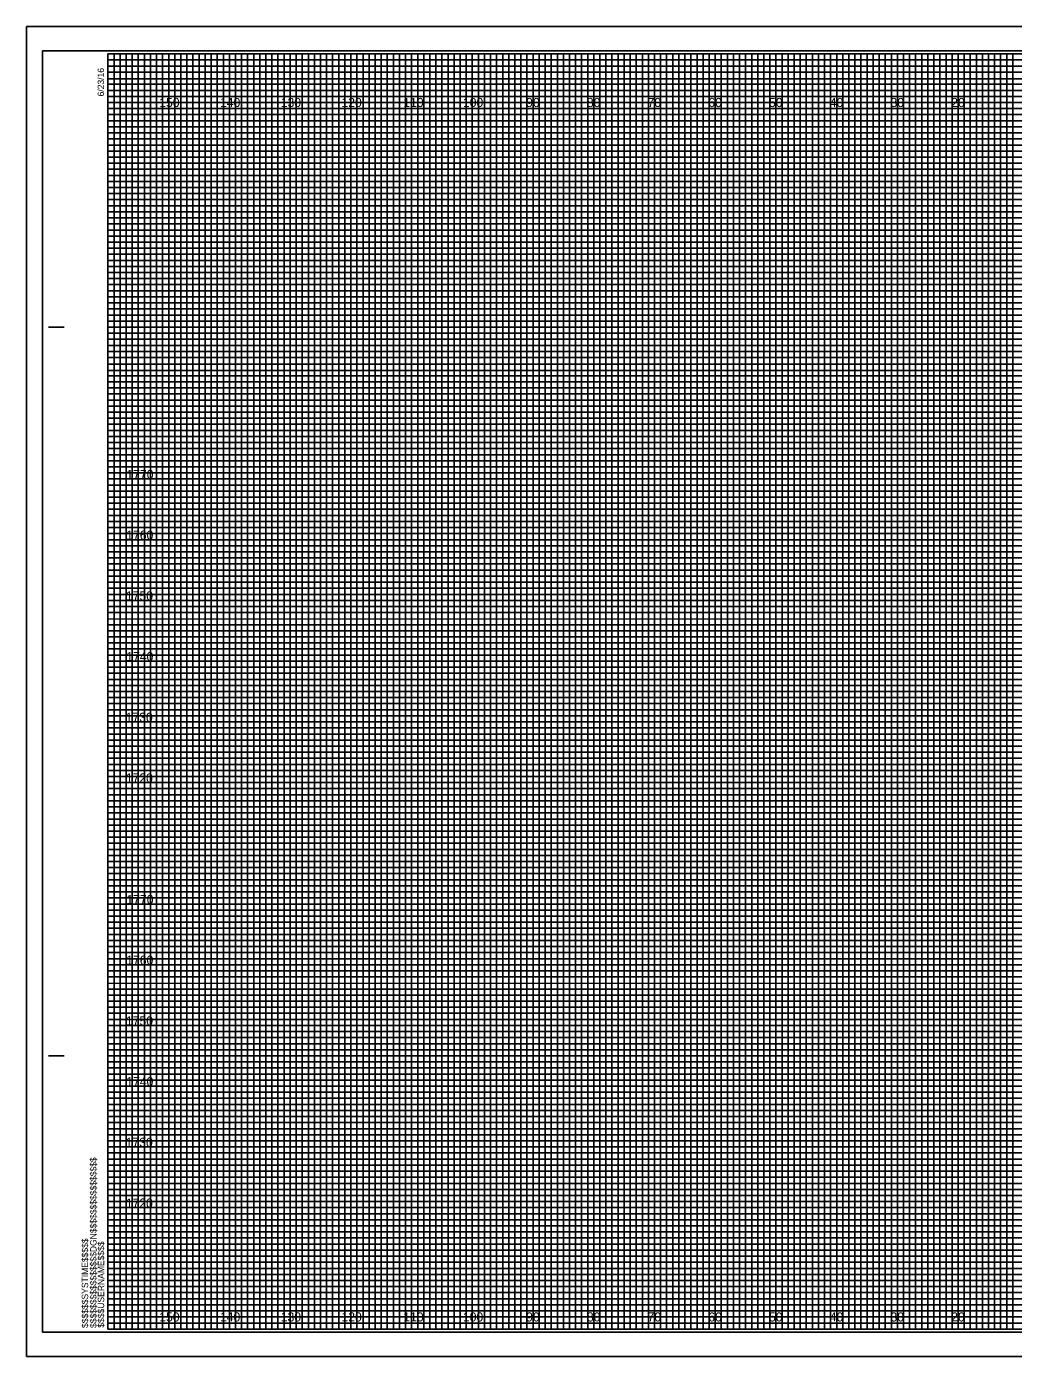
# Model space of a CAD drawing. Extents: x 570 to 907, y -9 to 870.
# Drawn here: x 570.4 to 732.9, y 210.6 to 429.6 of the extents above; entities that cross this region are included whole.
import ezdxf

# ---------------------------------------------------------------- set-up
doc = ezdxf.new("R2010")
doc.units = 0
for name, color, linetype in [('Prop XS Earthwork Shape', 7, 'Continuous'), ('Raster_Level_0', 7, 'Continuous'), ('Scratch_Level_3', 7, 'Continuous'), ('Sheet Cross Section CELL', 7, 'Continuous'), ('Sheet Cross Section Grid Middle CELL', 7, 'Continuous'), ('Sheet Cross Section Grid Minor 1 CELL', 7, 'Continuous'), ('Sheet Cross Section Grid Minor 2 CELL', 7, 'Continuous'), ('Sheet Cutting Line CELL', 7, 'Continuous'), ('Sheet DOT Grid CELL', 7, 'Continuous'), ('Sheet Plot Border Inside CELL', 7, 'Continuous'), ('Sheet Plot Border Outside CELL', 7, 'Continuous')]:
    doc.layers.add(name, color=color, linetype=linetype)

msp = doc.modelspace()

# ---------------------------------------------------------------- linework, layer by layer
at = {"layer": 'Prop XS Earthwork Shape'}
for p, q in [((593.77, 425.14), (583.77, 425.14)), ((593.77, 215.14), (593.77, 425.14)), ((613.77, 425.14), (603.77, 425.14)), ((603.77, 425.14), (603.77, 215.14)), ((613.77, 215.14), (613.77, 425.14)), ((633.77, 425.14), (623.77, 425.14)), ((623.77, 425.14), (623.77, 215.14)), ((633.77, 215.14), (633.77, 425.14)), ((653.77, 425.14), (643.77, 425.14)), ((643.77, 425.14), (643.77, 215.14)), ((653.77, 215.14), (653.77, 425.14)), ((673.77, 425.14), (663.77, 425.14)), ((663.77, 425.14), (663.77, 215.14)), ((673.77, 215.14), (673.77, 425.14)), ((693.77, 425.14), (683.77, 425.14)), ((683.77, 425.14), (683.77, 215.14)), ((693.77, 215.14), (693.77, 425.14)), ((713.77, 425.14), (703.77, 425.14)), ((703.77, 425.14), (703.77, 215.14)), ((713.77, 215.14), (713.77, 425.14)), ((733.77, 425.14), (723.77, 425.14)), ((723.77, 425.14), (723.77, 215.14)), ((603.77, 215.14), (593.77, 215.14)), ((623.77, 215.14), (613.77, 215.14)), ((643.77, 215.14), (633.77, 215.14)), ((663.77, 215.14), (653.77, 215.14)), ((683.77, 215.14), (673.77, 215.14)), ((703.77, 215.14), (693.77, 215.14)), ((723.77, 215.14), (713.77, 215.14))]:
    msp.add_line(p, q, dxfattribs=at)
for points in [[(583.77, 415.14), (903.77, 415.14), (903.77, 405.14), (583.77, 405.14)], [(583.77, 395.14), (903.77, 395.14), (903.77, 385.14), (583.77, 385.14)], [(583.77, 375.14), (903.77, 375.14), (903.77, 365.14), (583.77, 365.14)], [(583.77, 355.14), (903.77, 355.14), (903.77, 345.14), (583.77, 345.14)], [(583.77, 335.14), (903.77, 335.14), (903.77, 325.14), (583.77, 325.14)], [(583.77, 315.14), (903.77, 315.14), (903.77, 305.14), (583.77, 305.14)], [(583.77, 295.14), (903.77, 295.14), (903.77, 285.14), (583.77, 285.14)], [(583.77, 275.14), (903.77, 275.14), (903.77, 265.14), (583.77, 265.14)], [(583.77, 255.14), (903.77, 255.14), (903.77, 245.14), (583.77, 245.14)], [(583.77, 235.14), (903.77, 235.14), (903.77, 225.14), (583.77, 225.14)]]:
    msp.add_lwpolyline(points, dxfattribs=at)
at = {"layer": 'Sheet Cross Section CELL'}
for p, q in [((573.97, 380.14), (576.47, 380.14)), ((574.07, 380.14), (576.57, 380.14)), ((573.97, 260.14), (576.47, 260.14)), ((574.07, 260.14), (576.57, 260.14)), ((583.77, 215.14), (583.77, 215.14)), ((583.77, 215.14), (583.77, 215.14)), ((583.77, 215.14), (583.77, 215.14)), ((583.77, 215.14), (583.77, 215.14)), ((583.77, 215.14), (583.77, 215.14)), ((583.77, 215.14), (583.77, 215.14)), ((583.77, 215.14), (583.77, 215.14))]:
    msp.add_line(p, q, dxfattribs=at)
msp.add_lwpolyline([(903.77, 425.14), (583.77, 425.14), (583.77, 215.14), (903.77, 215.14)], close=True, dxfattribs=at)
at = {"layer": 'Sheet Cross Section Grid Middle CELL'}
for points in [[(583.77, 425.14), (588.77, 425.14), (588.77, 215.14), (598.77, 215.14), (598.77, 425.14), (608.77, 425.14), (608.77, 215.14), (618.77, 215.14), (618.77, 425.14), (628.77, 425.14), (628.77, 215.14), (638.77, 215.14), (638.77, 425.14), (648.77, 425.14), (648.77, 215.14), (658.77, 215.14), (658.77, 425.14), (668.77, 425.14), (668.77, 215.14), (678.77, 215.14), (678.77, 425.14), (688.77, 425.14), (688.77, 215.14), (698.77, 215.14), (698.77, 425.14), (708.77, 425.14), (708.77, 215.14), (718.77, 215.14), (718.77, 425.14), (728.77, 425.14), (728.77, 215.14), (738.77, 215.14)], [(583.77, 420.14), (858.77, 420.14)], [(583.77, 400.14), (903.77, 400.14), (903.77, 410.14), (583.77, 410.14)], [(583.77, 380.14), (903.77, 380.14), (903.77, 390.14), (583.77, 390.14)], [(583.77, 360.14), (903.77, 360.14), (903.77, 370.14), (583.77, 370.14)], [(583.77, 340.14), (903.77, 340.14), (903.77, 350.14), (583.77, 350.14)], [(583.77, 320.14), (903.77, 320.14), (903.77, 330.14), (583.77, 330.14)], [(583.77, 300.14), (903.77, 300.14), (903.77, 310.14), (583.77, 310.14)], [(583.77, 280.14), (903.77, 280.14), (903.77, 290.14), (583.77, 290.14)], [(583.77, 260.14), (903.77, 260.14), (903.77, 270.14), (583.77, 270.14)], [(583.77, 240.14), (903.77, 240.14), (903.77, 250.14), (583.77, 250.14)], [(583.77, 220.14), (903.77, 220.14), (903.77, 230.14), (583.77, 230.14)]]:
    msp.add_lwpolyline(points, dxfattribs=at)
at = {"layer": 'Sheet Cross Section Grid Minor 1 CELL'}
for p, q in [((583.77, 424.14), (843.77, 424.14)), ((843.77, 423.12), (583.77, 423.12)), ((583.77, 423.12), (583.77, 422.14)), ((583.77, 422.14), (843.77, 422.14)), ((843.77, 421.03), (583.77, 421.03)), ((583.77, 421.03), (583.77, 419.14)), ((583.77, 419.14), (903.77, 419.14))]:
    msp.add_line(p, q, dxfattribs=at)
for points in [[(583.77, 418.14), (853.77, 418.14), (903.77, 418.14), (903.77, 417.14), (583.77, 417.14)], [(583.77, 416.14), (903.77, 416.14), (903.77, 414.14), (583.77, 414.14)], [(583.77, 413.14), (903.77, 413.14), (903.77, 412.14), (583.77, 412.12)], [(583.77, 411.14), (903.77, 411.14), (903.77, 409.14), (583.77, 409.14)], [(583.77, 408.14), (903.77, 408.14), (903.77, 407.14), (583.77, 407.14)], [(583.77, 406.14), (903.77, 406.14), (903.77, 404.14), (583.77, 404.14)], [(583.77, 403.14), (903.77, 403.14), (903.77, 402.14), (583.77, 402.14)], [(583.77, 401.14), (903.77, 401.14), (903.77, 399.14), (583.77, 399.14)], [(583.77, 398.14), (903.77, 398.14), (903.77, 397.14), (583.77, 397.14)], [(583.77, 396.14), (903.77, 396.14), (903.77, 394.14), (583.77, 394.14)], [(583.77, 393.14), (903.77, 393.14), (903.77, 392.14), (583.77, 392.14)], [(583.77, 391.14), (903.77, 391.14), (903.77, 389.09), (903.77, 388.14), (903.77, 387.14), (583.77, 387.14)], [(583.77, 389.14), (903.77, 389.14), (903.77, 388.14), (583.77, 388.14)], [(583.77, 386.14), (903.77, 386.14), (903.77, 384.14), (583.77, 384.17)], [(583.77, 384.17), (903.77, 384.14), (903.77, 383.14), (583.77, 383.14)], [(583.77, 382.14), (903.77, 382.14), (903.77, 381.14), (583.77, 381.14)], [(583.77, 379.14), (903.77, 379.14), (903.77, 378.14), (583.77, 378.14)], [(583.77, 377.14), (903.77, 377.14), (903.77, 376.14), (583.77, 376.14)], [(583.7, 374.03), (903.77, 374.03), (903.77, 373.02), (583.7, 373.02)], [(583.77, 372.14), (903.77, 372.14), (903.77, 371.14), (583.77, 371.14)], [(583.77, 369.14), (903.77, 369.14), (903.77, 368.14), (583.77, 368.14)], [(583.77, 367.14), (903.77, 367.14), (903.77, 366.14), (583.77, 366.14)], [(583.77, 364.14), (903.77, 364.14), (903.77, 363.14), (583.77, 363.14)], [(583.77, 362.14), (903.77, 362.14), (903.77, 361.14), (583.77, 361.14)], [(583.77, 359.14), (903.77, 359.14), (903.77, 358.14), (583.77, 358.14)], [(583.77, 357.14), (903.77, 357.14), (903.77, 356.14), (583.77, 356.14)], [(583.77, 354.14), (903.77, 354.14), (903.76, 353.12), (583.77, 353.14)], [(583.77, 352.14), (903.77, 352.14), (903.77, 351.14), (583.77, 351.14)], [(583.77, 349.14), (903.77, 349.14), (903.77, 348.14), (583.77, 348.14)], [(583.77, 347.14), (903.77, 347.14), (903.77, 346.14), (583.77, 346.14)], [(583.77, 344.14), (903.77, 344.14), (903.77, 343.14), (583.77, 343.14)], [(583.77, 342.14), (903.77, 342.14), (903.77, 341.14), (583.77, 341.14)], [(583.77, 339.14), (903.77, 339.14), (903.77, 338.14), (583.77, 338.14)], [(583.77, 337.14), (903.77, 337.14), (903.77, 336.14), (583.77, 336.14)], [(583.77, 334.14), (903.77, 334.14), (903.77, 333.14), (583.77, 333.14)], [(583.77, 332.13), (903.84, 332.05), (903.77, 331.14), (583.77, 331.14)], [(583.77, 329.14), (903.77, 329.14), (903.77, 328.14), (583.77, 328.14)], [(583.77, 327.14), (903.77, 327.14), (903.77, 326.14), (583.77, 326.14)], [(583.77, 324.14), (903.77, 324.14), (903.77, 323.14), (583.77, 323.14)], [(583.77, 322.14), (903.77, 322.14), (903.77, 321.14), (583.77, 321.14)], [(583.77, 319.14), (903.77, 319.14), (903.77, 318.14), (583.77, 318.14)], [(583.77, 317.14), (903.77, 317.14), (903.77, 316.14), (583.77, 316.14)], [(583.77, 314.14), (903.77, 314.14), (903.77, 313.14), (583.77, 313.14)], [(583.77, 312.14), (903.77, 312.14), (903.77, 311.14), (583.77, 311.14)], [(583.77, 309.14), (903.77, 309.14), (903.77, 308.14), (583.77, 308.14)], [(583.77, 307.14), (903.77, 307.14), (903.77, 306.14), (583.77, 306.14)], [(583.77, 304.14), (903.77, 304.14), (903.77, 303.14), (583.77, 303.14)], [(583.77, 302.14), (903.77, 302.14), (903.77, 301.14), (583.77, 301.14)], [(583.77, 299.14), (903.77, 299.14), (903.77, 298.14), (583.77, 298.14)], [(583.77, 297.14), (903.77, 297.14), (903.77, 296.14), (583.77, 296.14)], [(583.77, 294.14), (903.77, 294.14), (903.76, 293.12), (583.77, 293.14)], [(583.77, 292.14), (903.77, 292.14), (903.77, 291.14), (583.77, 291.14)], [(583.77, 289.14), (903.77, 289.14), (903.77, 288.14), (583.77, 288.14)], [(583.77, 287.14), (903.77, 287.14), (903.77, 286.14), (583.77, 286.14)], [(583.77, 284.14), (903.77, 284.14), (903.77, 283.14), (583.77, 283.14)], [(583.77, 282.14), (903.77, 282.14), (903.77, 281.14), (583.77, 281.14)], [(583.77, 279.14), (903.77, 279.14), (903.77, 278.14), (583.77, 278.14)], [(583.77, 277.14), (903.77, 277.14), (903.77, 276.14), (583.77, 276.14)], [(583.77, 274.14), (903.77, 274.14), (903.77, 273.14), (583.77, 273.14)], [(583.77, 272.13), (903.84, 272.05), (903.77, 271.14), (583.77, 271.14)], [(583.77, 269.14), (903.77, 269.14), (903.77, 268.14), (583.77, 268.14)], [(583.77, 267.14), (903.77, 267.14), (903.77, 266.14), (583.77, 266.14)], [(583.77, 264.14), (903.77, 264.14), (903.77, 263.14), (583.77, 263.14)], [(583.77, 262.14), (903.77, 262.14), (903.77, 261.14), (583.77, 261.14)], [(583.77, 259.14), (903.77, 259.14), (903.77, 258.14), (583.77, 258.14)], [(583.77, 257.14), (903.77, 257.14), (903.77, 256.14), (583.77, 256.14)], [(583.77, 254.14), (903.77, 254.14), (903.77, 253.14), (583.77, 253.14)], [(583.77, 252.14), (903.77, 252.14), (903.77, 251.14), (583.77, 251.14)], [(583.77, 249.14), (903.77, 249.14), (903.77, 248.14), (583.77, 248.14)], [(583.77, 247.14), (903.77, 247.14), (903.77, 246.14), (583.77, 246.14)], [(583.77, 244.14), (903.77, 244.14), (903.77, 243.14), (583.77, 243.14)], [(583.77, 242.14), (903.77, 242.14), (903.77, 241.14), (583.77, 241.14)], [(583.77, 239.14), (903.77, 239.14), (903.77, 238.14), (583.77, 238.14)], [(583.77, 237.14), (903.77, 237.14), (903.77, 236.14), (583.77, 236.14)], [(583.77, 234.14), (903.77, 234.14), (903.77, 233.14), (583.77, 233.14)], [(583.77, 232.14), (903.77, 232.14), (903.77, 231.14), (583.77, 231.14)], [(583.77, 229.14), (903.77, 229.14), (903.77, 228.14), (583.77, 228.14)], [(583.77, 227.14), (903.77, 227.14), (903.77, 226.14), (583.77, 226.14)], [(583.77, 224.14), (903.77, 224.14), (903.77, 223.14), (583.77, 223.14)], [(583.77, 222.14), (903.77, 222.14), (903.77, 221.14), (583.77, 221.14)], [(583.77, 219.14), (903.77, 219.14), (903.77, 218.14), (583.77, 218.14)], [(583.77, 217.14), (903.77, 217.14), (903.77, 216.14), (583.77, 216.14)]]:
    msp.add_lwpolyline(points, dxfattribs=at)
at = {"layer": 'Sheet Cross Section Grid Minor 2 CELL'}
for points in [[(583.77, 215.14), (584.77, 215.14), (584.77, 425.14), (585.77, 425.14), (585.77, 215.14)], [(585.77, 215.14), (586.77, 215.14), (586.77, 425.14), (587.77, 425.14), (587.77, 215.14)], [(588.77, 215.14), (589.77, 215.14), (589.77, 425.14), (590.77, 425.14), (590.77, 215.14)], [(590.77, 215.14), (591.77, 215.14), (591.77, 425.14), (592.77, 425.14), (592.77, 215.14)], [(593.77, 215.14), (594.77, 215.14), (594.77, 425.14), (595.77, 425.14), (595.77, 215.14)], [(595.77, 215.14), (596.77, 215.14), (596.77, 425.14), (597.77, 425.14), (597.77, 215.14)], [(598.77, 215.14), (599.77, 215.14), (599.77, 425.14), (600.77, 425.14), (600.77, 215.14)], [(600.77, 215.14), (601.77, 215.14), (601.77, 425.14), (602.77, 425.14), (602.77, 215.14)], [(603.77, 215.14), (604.77, 215.14), (604.77, 425.14), (605.77, 425.14), (605.77, 215.14)], [(605.77, 215.14), (606.77, 215.14), (606.77, 425.14), (607.77, 425.14), (607.77, 215.14)], [(608.77, 215.14), (609.77, 215.14), (609.77, 425.14), (610.77, 425.14), (610.77, 215.14)], [(610.77, 215.14), (611.77, 215.14), (611.77, 425.14), (612.77, 425.14), (612.77, 215.14)], [(613.77, 215.14), (614.77, 215.14), (614.77, 425.14), (615.77, 425.14), (615.77, 215.14)], [(615.77, 215.14), (616.77, 215.14), (616.77, 425.14), (617.77, 425.14), (617.77, 215.14)], [(618.77, 215.14), (619.77, 215.14), (619.77, 425.14), (620.77, 425.14), (620.77, 215.14)], [(620.77, 215.14), (621.77, 215.14), (621.77, 425.14), (622.77, 425.14), (622.77, 215.14)], [(623.77, 215.14), (624.77, 215.14), (624.77, 425.14), (625.77, 425.14), (625.77, 215.14)], [(625.77, 215.14), (626.77, 215.14), (626.77, 425.14), (627.77, 425.14), (627.77, 215.14)], [(628.77, 215.14), (629.77, 215.14), (629.77, 425.14), (630.77, 425.14), (630.77, 215.14)], [(630.77, 215.14), (631.77, 215.14), (631.77, 425.14), (632.77, 425.14), (632.77, 215.14)], [(633.77, 215.14), (634.77, 215.14), (634.77, 425.14), (635.77, 425.14), (635.77, 215.14)], [(635.77, 215.14), (636.77, 215.14), (636.77, 425.14), (637.77, 425.14), (637.77, 215.14)], [(638.77, 215.14), (639.77, 215.14), (639.77, 425.14), (640.77, 425.14), (640.77, 215.14)], [(640.77, 215.14), (641.77, 215.14), (641.77, 425.14), (642.77, 425.14), (642.77, 215.14)], [(643.77, 215.14), (644.77, 215.14), (644.77, 425.14), (645.77, 425.14), (645.77, 215.14)], [(645.77, 215.14), (646.77, 215.14), (646.77, 425.14), (647.77, 425.14), (647.77, 215.14)], [(648.77, 215.14), (649.77, 215.14), (649.77, 425.14), (650.77, 425.14), (650.77, 215.14)], [(650.77, 215.14), (651.77, 215.14), (651.77, 425.14), (652.77, 425.14), (652.77, 215.14)], [(653.77, 215.14), (654.77, 215.14), (654.77, 425.14), (655.77, 425.14), (655.77, 215.14)], [(655.77, 215.14), (656.77, 215.14), (656.77, 425.14), (657.77, 425.14), (657.77, 215.14)], [(658.77, 215.14), (659.77, 215.14), (659.77, 425.14), (660.77, 425.14), (660.77, 215.14)], [(660.77, 215.14), (661.77, 215.14), (661.77, 425.14), (662.77, 425.14), (662.77, 215.14)], [(663.77, 215.14), (664.77, 215.14), (664.77, 425.14), (665.77, 425.14), (665.77, 215.14)], [(665.77, 215.14), (666.77, 215.14), (666.77, 425.14), (667.77, 425.14), (667.77, 215.14)], [(668.77, 215.14), (669.77, 215.14), (669.77, 425.14), (670.77, 425.14), (670.77, 215.14)], [(670.77, 215.14), (671.77, 215.14), (671.77, 425.14), (672.77, 425.14), (672.77, 215.14)], [(673.77, 215.14), (674.77, 215.14), (674.77, 425.14), (675.77, 425.14), (675.77, 215.14)], [(675.77, 215.14), (676.77, 215.14), (676.77, 425.14), (677.77, 425.14), (677.77, 215.14)], [(678.77, 215.14), (679.77, 215.14), (679.77, 425.14), (680.77, 425.14), (680.77, 215.14)], [(680.77, 215.14), (681.77, 215.14), (681.77, 425.14), (682.77, 425.14), (682.77, 215.14)], [(683.77, 215.14), (684.77, 215.14), (684.77, 425.14), (685.77, 425.14), (685.77, 215.14)], [(685.77, 215.14), (686.77, 215.14), (686.77, 425.14), (687.77, 425.14), (687.77, 215.14)], [(688.77, 215.14), (689.77, 215.14), (689.77, 425.14), (690.77, 425.14), (690.77, 215.14)], [(690.77, 215.14), (691.77, 215.14), (691.77, 425.14), (692.77, 425.14), (692.77, 215.14)], [(693.77, 215.14), (694.77, 215.14), (694.77, 425.14), (695.77, 425.14), (695.77, 215.14)], [(695.77, 215.14), (696.77, 215.14), (696.77, 425.14), (697.77, 425.14), (697.77, 215.14)], [(698.77, 215.14), (699.77, 215.14), (699.77, 425.14), (700.77, 425.14), (700.77, 215.14)], [(700.77, 215.14), (701.77, 215.14), (701.77, 425.14), (702.77, 425.14), (702.77, 215.14)], [(703.77, 215.14), (704.77, 215.14), (704.77, 425.14), (705.77, 425.14), (705.77, 215.14)], [(705.77, 215.14), (706.77, 215.14), (706.77, 425.14), (707.77, 425.14), (707.77, 215.14)], [(708.77, 215.14), (709.77, 215.14), (709.77, 425.14), (710.77, 425.14), (710.77, 215.14)], [(710.77, 215.14), (711.77, 215.14), (711.77, 425.14), (712.77, 425.14), (712.77, 215.14)], [(713.77, 215.14), (714.77, 215.14), (714.77, 425.14), (715.77, 425.14), (715.77, 215.14)], [(715.77, 215.14), (716.77, 215.14), (716.77, 425.14), (717.77, 425.14), (717.77, 215.14)], [(718.77, 215.14), (719.77, 215.14), (719.77, 425.14), (720.77, 425.14), (720.77, 215.14)], [(720.77, 215.14), (721.77, 215.14), (721.77, 425.14), (722.77, 425.14), (722.77, 215.14)], [(723.77, 215.14), (724.77, 215.14), (724.77, 425.14), (725.77, 425.14), (725.77, 215.14)], [(725.77, 215.14), (726.77, 215.14), (726.77, 425.14), (727.77, 425.14), (727.77, 215.14)], [(728.77, 215.14), (729.77, 215.14), (729.77, 425.14), (730.77, 425.14), (730.77, 215.14)], [(730.77, 215.14), (731.77, 215.14), (731.77, 425.14), (732.77, 425.14), (732.77, 215.14)]]:
    msp.add_lwpolyline(points, dxfattribs=at)
at = {"layer": 'Sheet Cutting Line CELL'}
for p, q in [((907.07, 429.64), (570.37, 429.64)), ((570.37, 429.64), (570.37, 210.64)), ((570.37, 210.64), (907.07, 210.64))]:
    msp.add_line(p, q, dxfattribs=at)
at = {"layer": 'Sheet DOT Grid CELL'}
for p, q in [((593.77, 215.14), (593.77, 425.14)), ((603.77, 215.14), (603.77, 425.14)), ((613.77, 215.14), (613.77, 425.14)), ((623.77, 215.14), (623.77, 425.14)), ((633.77, 215.14), (633.77, 425.14)), ((643.77, 215.14), (643.77, 425.14)), ((653.77, 215.14), (653.77, 425.14)), ((663.77, 215.14), (663.77, 425.14)), ((673.77, 215.14), (673.77, 425.14)), ((683.77, 215.14), (683.77, 425.14)), ((693.77, 215.14), (693.77, 425.14)), ((703.77, 215.14), (703.77, 425.14)), ((713.77, 215.14), (713.77, 425.14)), ((723.77, 215.14), (723.77, 425.14)), ((583.77, 415.14), (903.77, 415.14)), ((583.77, 405.14), (903.77, 405.14)), ((583.77, 395.14), (903.77, 395.14)), ((583.77, 385.14), (903.77, 385.14)), ((583.77, 375.14), (903.77, 375.14)), ((583.77, 365.14), (903.77, 365.14)), ((583.77, 355.14), (903.77, 355.14)), ((583.77, 345.14), (903.77, 345.14)), ((583.77, 335.14), (903.77, 335.14)), ((583.77, 325.14), (903.77, 325.14)), ((583.77, 315.14), (903.77, 315.14)), ((583.77, 305.14), (903.77, 305.14)), ((583.77, 295.14), (903.77, 295.14)), ((583.77, 285.14), (903.77, 285.14)), ((583.77, 275.14), (903.77, 275.14)), ((583.77, 265.14), (903.77, 265.14)), ((583.77, 255.14), (903.77, 255.14)), ((583.77, 245.14), (903.77, 245.14)), ((583.77, 235.14), (903.77, 235.14)), ((583.77, 225.14), (903.77, 225.14))]:
    msp.add_line(p, q, dxfattribs=at)
at = {"layer": 'Sheet Plot Border Inside CELL'}
msp.add_lwpolyline([(572.97, 214.64), (906.17, 214.64), (906.17, 425.64), (572.97, 425.64)], close=True, dxfattribs=at)
at = {"layer": 'Sheet Plot Border Outside CELL'}
msp.add_lwpolyline([(570.37, 210.64), (907.07, 210.64), (907.07, 429.64), (570.37, 429.64)], close=True, dxfattribs=at)

# ---------------------------------------------------------------- texts
at = {"layer": 'Raster_Level_0'}
for s, p in [('150', (592.22, 416.39)), ('140', (602.22, 416.39)), ('130', (612.22, 416.39)), ('120', (622.22, 416.39)), ('110', (632.4, 416.39)), ('100', (642.22, 416.39)), ('90', (652.63, 416.39)), ('80', (662.63, 416.39)), ('70', (672.63, 416.39)), ('60', (682.63, 416.39)), ('50', (692.63, 416.39)), ('40', (702.63, 416.39)), ('30', (712.63, 416.39)), ('20', (722.63, 416.39)), ('150', (592.22, 216.39)), ('140', (602.22, 216.39)), ('130', (612.22, 216.39)), ('120', (622.22, 216.39)), ('110', (632.4, 216.39)), ('100', (642.22, 216.39)), ('90', (652.63, 216.39)), ('80', (662.63, 216.39)), ('70', (672.63, 216.39)), ('60', (682.63, 216.39)), ('50', (692.63, 216.39)), ('40', (702.63, 216.39)), ('30', (712.63, 216.39)), ('20', (722.63, 216.39))]:
    msp.add_text(s, height=1.5, dxfattribs=at).set_placement(p)
at = {"layer": 'Scratch_Level_3'}
for s, p in [('1770', (586.81, 355.14)), ('1760', (586.78, 345.14)), ('1750', (586.73, 335.14)), ('1740', (586.78, 325.14)), ('1730', (586.69, 315.14)), ('1720', (586.71, 305.14)), ('1770', (586.81, 285.14)), ('1760', (586.78, 275.14)), ('1750', (586.73, 265.14)), ('1740', (586.78, 255.14)), ('1730', (586.69, 245.14)), ('1720', (586.71, 235.14))]:
    msp.add_text(s, height=1.5, dxfattribs=at).set_placement(p)
at = {"layer": 'Sheet Cross Section CELL'}
for s, p in [('6/23/16', (583.12, 418.14)), ('$$$$$$$$$$$$$$$$DGN$$$$$$$$$$$$$$$$', (581.89, 215.32)), ('$$$$$$SYSTIME$$$$$', (580.51, 215.32)), ('$$$$USERNAME$$$$', (583.15, 215.37))]:
    msp.add_text(s, height=1.05, rotation=90, dxfattribs=at).set_placement(p)

doc.saveas('drawing.dxf')
